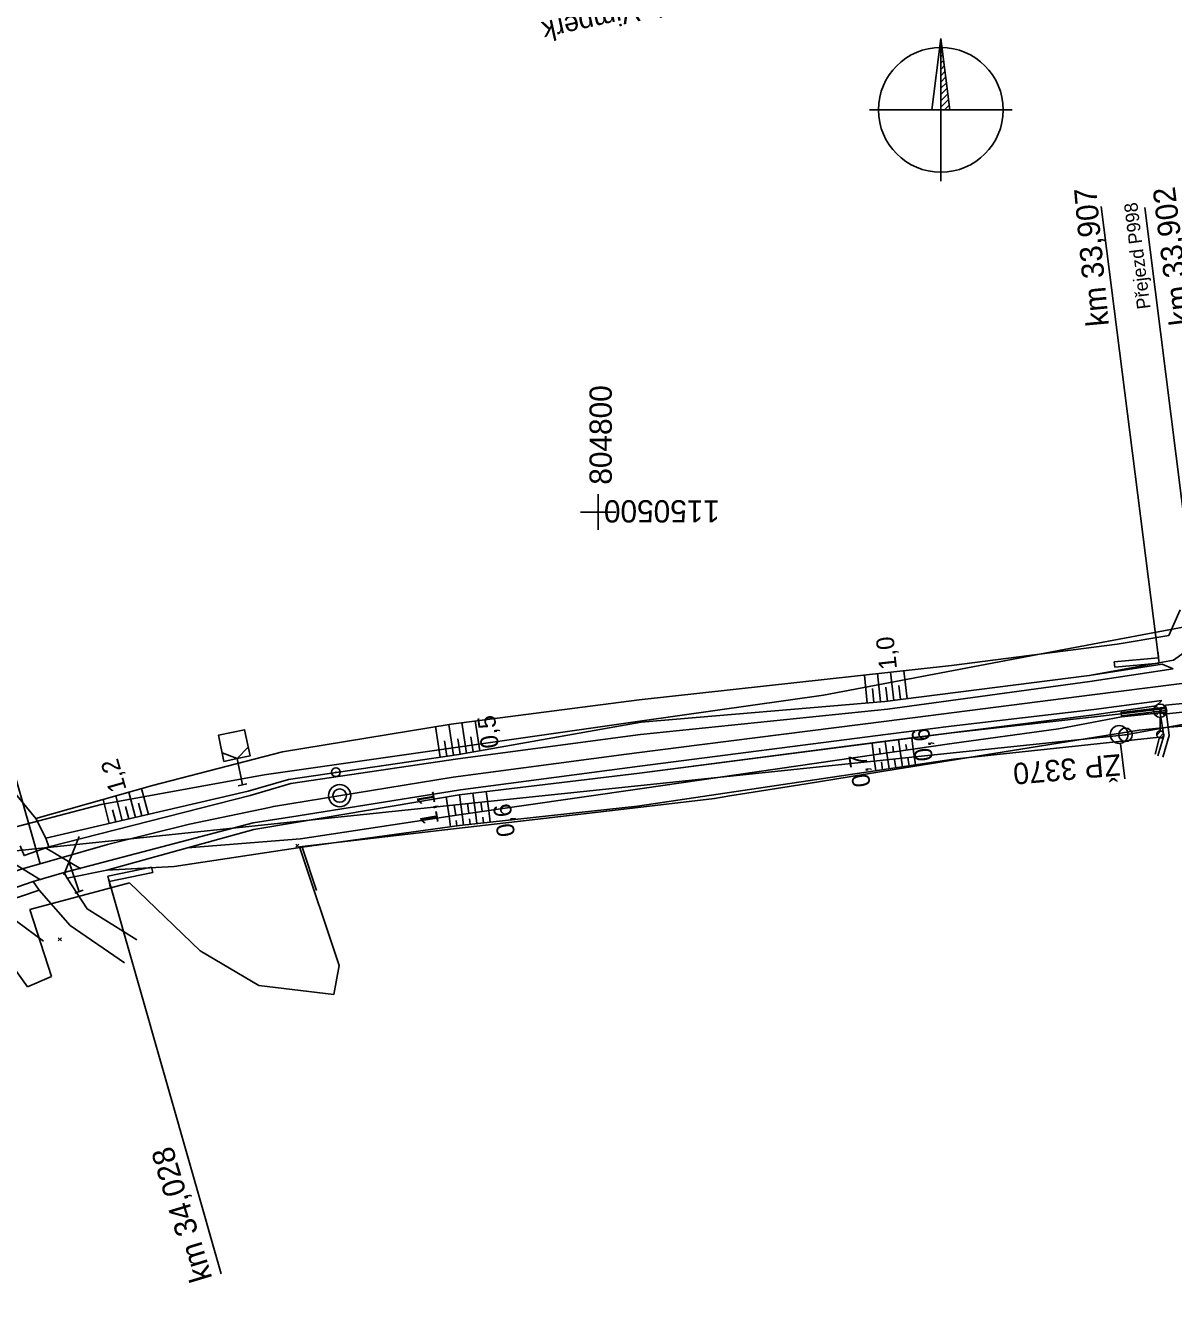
# Model space of a CAD drawing. Extents: x -805730 to -804640, y -1150889 to -1150366.
# Drawn here: x -804864.2 to -804735.5, y -1150590.3 to -1150445.4 of the extents above; entities that cross this region are included whole.
import ezdxf

# ---------------------------------------------------------------- set-up
doc = ezdxf.new("R2010")
doc.units = 0
for name, color, linetype in [('0381KM032-037P - Vrstva 1', 7, 'Continuous'), ('0381KM032-037P - Vrstva 13', 7, 'Continuous'), ('0381KM032-037P - Vrstva 17', 7, 'Continuous'), ('0381KM032-037P - Vrstva 25', 7, 'Continuous'), ('0381KM032-037P - Vrstva 36', 7, 'Continuous'), ('0381KM032-037P - Vrstva 4', 7, 'Continuous'), ('0381KM032-037P - Vrstva 43', 7, 'Continuous'), ('0381KM032-037P - Vrstva 48', 7, 'Continuous'), ('0381KM032-037P - Vrstva 49', 7, 'Continuous'), ('0381KM032-037P - Vrstva 51', 7, 'Continuous'), ('0381KM032-037P - Vrstva 7', 7, 'Continuous'), ('0381KM032-037P - Vrstva 9', 7, 'Continuous'), ('formát', 7, 'Continuous'), ('hran DP - hran DP', 7, 'Continuous'), ('krizky_1000 - souradnice', 7, 'Continuous'), ('krizky_1000 - Vrstva 1', 7, 'Continuous'), ('legenda - Vrstva 7', 7, 'Continuous'), ('vyt_sit - polygon', 7, 'Continuous'), ('vyt_sit - stávající', 7, 'Continuous')]:
    doc.layers.add(name, color=color, linetype=linetype)

msp = doc.modelspace()

# ---------------------------------------------------------------- linework, layer by layer
at = {"layer": '0381KM032-037P - Vrstva 1'}
for points in [[(-804673.35, -1150511.49), (-804675.7, -1150511.78), (-804698.85, -1150514.71), (-804701.61, -1150515.06), (-804722.18, -1150517.67), (-804729.05, -1150518.54), (-804735.1, -1150519.31), (-804744.56, -1150520.5), (-804767.65, -1150523.46), (-804791, -1150526.42)], [(-804791, -1150526.42), (-804796.82, -1150527.16), (-804816.26, -1150529.72), (-804836.43, -1150533.03), (-804836.89, -1150533.13)], [(-804836.89, -1150533.13), (-804845.84, -1150535.01), (-804855.06, -1150537.3), (-804860.78, -1150538.93), (-804864.46, -1150539.98), (-804872.35, -1150542.54)]]:
    msp.add_lwpolyline(points, dxfattribs=at)
at = {"layer": '0381KM032-037P - Vrstva 13'}
msp.add_line((-804736.93, -1150522.56), (-804736.22, -1150522.62), dxfattribs=at)
for points in [[(-804736.32, -1150521.88), (-804741.33, -1150522.48), (-804741.32, -1150522.62), (-804736.39, -1150522.04)], [(-804736.33, -1150522.27), (-804741.29, -1150522.87), (-804741.32, -1150522.62)], [(-804741.29, -1150522.87), (-804741.28, -1150522.98), (-804736.24, -1150522.43)], [(-804736.93, -1150522.56), (-804736.54, -1150525.1), (-804737.22, -1150527.34)], [(-804736.22, -1150522.62), (-804735.92, -1150525.05), (-804736.64, -1150527.49)], [(-804736.32, -1150521.88), (-804736.39, -1150522.04), (-804736.33, -1150522.27), (-804736.24, -1150522.43)]]:
    msp.add_lwpolyline(points, dxfattribs=at)
at = {"layer": '0381KM032-037P - Vrstva 17'}
msp.add_line((-804831.6, -1150542.45), (-804833.23, -1150537.58), dxfattribs=at)
for points in [[(-804734.71, -1150510.96), (-804735.96, -1150513.84), (-804741.77, -1150514.83), (-804760.36, -1150517.2), (-804795.4, -1150521.06), (-804816.51, -1150523.78), (-804835.4, -1150526.88), (-804850, -1150530.66), (-804863.08, -1150534.36), (-804866.23, -1150530.55), (-804868.05, -1150528.28)], [(-804833.23, -1150537.58), (-804815.54, -1150535.16), (-804795.6, -1150532.98), (-804760.14, -1150527.72), (-804737.02, -1150525.24), (-804737.52, -1150527.15)]]:
    msp.add_lwpolyline(points, dxfattribs=at)
at = {"layer": '0381KM032-037P - Vrstva 25'}
for p, q in [((-804737.43, -1150521.73), (-804736.43, -1150522.84)), ((-804737.41, -1150522.86), (-804736.43, -1150521.74)), ((-804736.93, -1150523.04), (-804736.93, -1150524.54)), ((-804737.32, -1150525.02), (-804736.85, -1150524.55)), ((-804737.06, -1150525.32), (-804736.56, -1150524.82))]:
    msp.add_line(p, q, dxfattribs=at)
for centre, radius in [((-804736.94, -1150522.29), 0.749), ((-804736.93, -1150524.94), 0.4), ((-804736.93, -1150524.94), 0.4)]:
    msp.add_circle(centre, radius, dxfattribs=at)
at = {"layer": '0381KM032-037P - Vrstva 36'}
for p, q in [((-804741.54, -1150524.95), (-804741.54, -1150524.95)), ((-804741.41, -1150525.95), (-804740.91, -1150529.91))]:
    msp.add_line(p, q, dxfattribs=at)
msp.add_circle((-804741.54, -1150524.95), 1, dxfattribs=at)
at = {"layer": '0381KM032-037P - Vrstva 4'}
for p, q in [((-804738.68, -1150465.82), (-804731.99, -1150518.9)), ((-804874.8, -1150496.75), (-804862.62, -1150539.46)), ((-804862.01, -1150537.68), (-804858.05, -1150540.04)), ((-804859.94, -1150540.68), (-804858.22, -1150536.4)), ((-804862.58, -1150541.24), (-804866.52, -1150538.84)), ((-804858.24, -1150542.59), (-804859.36, -1150539.27)), ((-804854.94, -1150541.15), (-804854.94, -1150541.15)), ((-804858.72, -1150542.75), (-804857.77, -1150542.43))]:
    msp.add_line(p, q, dxfattribs=at)
for points in [[(-804735.49, -1150517.59), (-804736.73, -1150517.05), (-804744.9, -1150518.34), (-804767.83, -1150521.26)], [(-804735.49, -1150517.59), (-804744.82, -1150519), (-804767.55, -1150522.1)], [(-804767.83, -1150521.26), (-804795.17, -1150523.55), (-804815.65, -1150527.19), (-804834.76, -1150530), (-804839.27, -1150531.31), (-804861.98, -1150536.58), (-804861.64, -1150537.54)], [(-804736.74, -1150521.15), (-804737.38, -1150521.73), (-804744.34, -1150522.73), (-804767.48, -1150525.67)], [(-804736.74, -1150521.15), (-804744.39, -1150522.13), (-804760.4, -1150524), (-804767.46, -1150524.91)], [(-804767.55, -1150522.1), (-804795.24, -1150524.96), (-804815.73, -1150527.69), (-804834.48, -1150530.44), (-804839.03, -1150531.78), (-804861.64, -1150537.54)], [(-804767.46, -1150524.91), (-804795.31, -1150528.51), (-804815.46, -1150531.15), (-804833.67, -1150534.06), (-804838.71, -1150534.85), (-804859.92, -1150540.42), (-804859.57, -1150541.07)], [(-804767.48, -1150525.67), (-804795.35, -1150529.3), (-804815.58, -1150531.71), (-804833.51, -1150534.75), (-804838.64, -1150535.6), (-804846.07, -1150537.67)], [(-804859.57, -1150541.07), (-804855.14, -1150540.16), (-804846.07, -1150537.67)], [(-804862.73, -1150542.41), (-804863.39, -1150541.46), (-804892.29, -1150551.48), (-804910.22, -1150558.86), (-804951.61, -1150576.23), (-804993.7, -1150593.96), (-805038.63, -1150612.92), (-805049.62, -1150617.53), (-805055.59, -1150619.94), (-805066.74, -1150624.75), (-805096.44, -1150637.01)], [(-804864.94, -1150543.15), (-804862.73, -1150542.41), (-804862.73, -1150542.41)]]:
    msp.add_lwpolyline(points, dxfattribs=at)
at = {"layer": '0381KM032-037P - Vrstva 43'}
msp.add_lwpolyline([(-804736.33, -1150521.65), (-804729.5, -1150520.98), (-804729.45, -1150521.92), (-804736.22, -1150522.62)], close=True, dxfattribs=at)
at = {"layer": '0381KM032-037P - Vrstva 48'}
for p, q in [((-804769.83, -1150521.43), (-804770.13, -1150518.28)), ((-804768.33, -1150521.3), (-804768.64, -1150518.12)), ((-804766.81, -1150521.13), (-804767.19, -1150517.96)), ((-804765.32, -1150520.94), (-804765.7, -1150517.79)), ((-804769.08, -1150521.37), (-804769.23, -1150519.78)), ((-804767.55, -1150521.23), (-804767.74, -1150519.63)), ((-804766.07, -1150521.04), (-804766.25, -1150519.46)), ((-804817.72, -1150527.49), (-804818.25, -1150524.06)), ((-804816.23, -1150527.27), (-804816.77, -1150523.82)), ((-804814.76, -1150527.03), (-804815.28, -1150523.62)), ((-804813.28, -1150526.77), (-804813.79, -1150523.43)), ((-804816.97, -1150527.38), (-804817.24, -1150525.66)), ((-804815.5, -1150527.16), (-804815.76, -1150525.44)), ((-804814.02, -1150526.9), (-804814.28, -1150525.21)), ((-804769.09, -1150527.24), (-804769.27, -1150525.92)), ((-804767.6, -1150527.03), (-804767.78, -1150525.73)), ((-804766.12, -1150526.81), (-804766.3, -1150525.53)), ((-804765.38, -1150526.7), (-804765.46, -1150526.07)), ((-804764.64, -1150526.59), (-804764.81, -1150525.34)), ((-804768.83, -1150529.01), (-804769.09, -1150527.24)), ((-804768.35, -1150527.13), (-804768.44, -1150526.48)), ((-804767.35, -1150528.79), (-804767.61, -1150527.03)), ((-804766.86, -1150526.92), (-804766.95, -1150526.27)), ((-804765.87, -1150528.57), (-804766.12, -1150526.81)), ((-804765.12, -1150528.46), (-804765.25, -1150527.58)), ((-804764.38, -1150528.35), (-804764.64, -1150526.59)), ((-804768.09, -1150528.9), (-804768.22, -1150528.02)), ((-804766.61, -1150528.68), (-804766.74, -1150527.8)), ((-804853.39, -1150534.59), (-804854.11, -1150531.82)), ((-804851.93, -1150534.25), (-804852.66, -1150531.42)), ((-804850.47, -1150533.91), (-804851.22, -1150531.01)), ((-804815.25, -1150533.89), (-804815.54, -1150531.71)), ((-804813.77, -1150533.68), (-804814.05, -1150531.53)), ((-804812.28, -1150533.47), (-804812.56, -1150531.35)), ((-804854.85, -1150534.93), (-804855.55, -1150532.23)), ((-804854.12, -1150534.76), (-804854.48, -1150533.4)), ((-804852.66, -1150534.42), (-804853.02, -1150533.02)), ((-804851.2, -1150534.08), (-804851.57, -1150532.65)), ((-804816.7, -1150534.11), (-804817.05, -1150531.96)), ((-804815.96, -1150534), (-804816.14, -1150532.92)), ((-804814.51, -1150533.79), (-804814.65, -1150532.7)), ((-804813.02, -1150533.57), (-804813.16, -1150532.51)), ((-804816.58, -1150535.3), (-804816.73, -1150534.11)), ((-804815.84, -1150535.2), (-804815.92, -1150534.6)), ((-804815.1, -1150535.11), (-804815.25, -1150533.89)), ((-804814.35, -1150535.03), (-804814.43, -1150534.41)), ((-804813.6, -1150534.95), (-804813.76, -1150533.68)), ((-804812.86, -1150534.87), (-804812.94, -1150534.22)), ((-804812.11, -1150534.78), (-804812.28, -1150533.47))]:
    msp.add_line(p, q, dxfattribs=at)
at = {"layer": '0381KM032-037P - Vrstva 49'}
for p, q in [((-804861.98, -1150536.58), (-804863.08, -1150534.36)), ((-804833.93, -1150537.24), (-804833.57, -1150537.6)), ((-804833.57, -1150537.24), (-804833.92, -1150537.6)), ((-804855.14, -1150540.16), (-804859.57, -1150541.07)), ((-804860.23, -1150547.75), (-804860.58, -1150548.11)), ((-804860.58, -1150547.76), (-804860.23, -1150548.11))]:
    msp.add_line(p, q, dxfattribs=at)
for points in [[(-804731.33, -1150510.42), (-804733.06, -1150514.89), (-804735.43, -1150516.61), (-804744.9, -1150518.34), (-804767.83, -1150521.26), (-804795.17, -1150523.55), (-804815.65, -1150527.19), (-804834.76, -1150530), (-804839.27, -1150531.31), (-804861.98, -1150536.58)], [(-804735.96, -1150513.84), (-804741.77, -1150514.83), (-804760.36, -1150517.2), (-804795.4, -1150521.06), (-804816.51, -1150523.78), (-804835.4, -1150526.88), (-804850, -1150530.66), (-804863.08, -1150534.36)], [(-804741.32, -1150522.62), (-804760.31, -1150524.76), (-804795.35, -1150529.3), (-804815.58, -1150531.71), (-804833.51, -1150534.75), (-804838.64, -1150535.6), (-804846.07, -1150537.67)], [(-804846.07, -1150537.67), (-804833.4, -1150536.66), (-804815.63, -1150533.95), (-804795.08, -1150531.02), (-804760.31, -1150525.97), (-804748.35, -1150524.3), (-804741.28, -1150522.98)], [(-804741.32, -1150522.62), (-804741.29, -1150522.87), (-804741.28, -1150522.98)], [(-804737.02, -1150525.24), (-804760.14, -1150527.72), (-804795.6, -1150532.98), (-804815.54, -1150535.16), (-804833.23, -1150537.58)], [(-804833.23, -1150537.58), (-804847.59, -1150539.77), (-804855.14, -1150540.16)], [(-804859.57, -1150541.07), (-804857.34, -1150544.52), (-804851.77, -1150547.99)], [(-804869.27, -1150544.65), (-804865.03, -1150543.19), (-804864.94, -1150543.15), (-804862.73, -1150542.41)], [(-804862.73, -1150542.41), (-804859.23, -1150546.38), (-804853.15, -1150550.59)], [(-804865.78, -1150545.2), (-804865.26, -1150545.89), (-804862.25, -1150548.13)]]:
    msp.add_lwpolyline(points, dxfattribs=at)
at = {"layer": '0381KM032-037P - Vrstva 51'}
msp.add_line((-804861.98, -1150536.58), (-804863.08, -1150534.36), dxfattribs=at)
for points in [[(-804736.22, -1150522.62), (-804735.92, -1150525.05), (-804736.64, -1150527.49)], [(-804861.98, -1150536.58), (-804861.64, -1150537.54), (-804864.42, -1150538.53), (-804864.84, -1150537.45)], [(-804859.57, -1150541.07), (-804859.92, -1150540.42), (-804863.39, -1150541.46), (-804862.73, -1150542.41)], [(-804859.57, -1150541.07), (-804857.34, -1150544.52), (-804851.77, -1150547.99)], [(-804853.15, -1150550.59), (-804859.23, -1150546.38), (-804862.73, -1150542.41)]]:
    msp.add_lwpolyline(points, dxfattribs=at)
at = {"layer": '0381KM032-037P - Vrstva 7'}
for p, q in [((-804840.52, -1150527.66), (-804839.9, -1150530.59)), ((-804840.39, -1150530.7), (-804839.41, -1150530.49)), ((-804829.48, -1150529.18), (-804829.38, -1150529.18))]:
    msp.add_line(p, q, dxfattribs=at)
for points in [[(-804840.52, -1150527.66), (-804839.05, -1150527.35), (-804839.67, -1150524.41), (-804842.6, -1150525.03), (-804841.99, -1150527.97), (-804840.52, -1150527.66)], [(-804842.19, -1150526.99), (-804840.52, -1150527.66), (-804839.26, -1150526.37)]]:
    msp.add_lwpolyline(points, dxfattribs=at)
for centre, radius in [((-804829.43, -1150529.18), 0.5), ((-804829, -1150531.81), 1.25), ((-804829, -1150531.81), 0.752)]:
    msp.add_circle(centre, radius, dxfattribs=at)
at = {"layer": '0381KM032-037P - Vrstva 9'}
for p, q in [((-804737.08, -1150516.65), (-804743.56, -1150465.71)), ((-804737.11, -1150516.35), (-804737.17, -1150515.76)), ((-804737.11, -1150516.35), (-804742.09, -1150516.81)), ((-804742.09, -1150516.81), (-804742.04, -1150517.41)), ((-804742.04, -1150517.41), (-804737.06, -1150516.95)), ((-804737.06, -1150516.95), (-804737.11, -1150516.35)), ((-804850.11, -1150539.83), (-804855, -1150540.85)), ((-804854.88, -1150541.44), (-804849.98, -1150540.42)), ((-804849.98, -1150540.42), (-804850.11, -1150539.83)), ((-804855, -1150540.85), (-804854.88, -1150541.44)), ((-804854.94, -1150541.15), (-804842.3, -1150585.48)), ((-804854.88, -1150541.44), (-804854.75, -1150542.03))]:
    msp.add_line(p, q, dxfattribs=at)
at = {"layer": 'formát'}
for p, q in [((-804761.55, -1150446.86), (-804761.55, -1150462.86)), ((-804761.55, -1150447.49), (-804761.48, -1150447.42)), ((-804761.55, -1150448.2), (-804761.41, -1150448.05)), ((-804761.55, -1150448.91), (-804761.33, -1150448.68)), ((-804761.55, -1150449.61), (-804761.25, -1150449.31)), ((-804761.55, -1150450.32), (-804761.17, -1150449.94)), ((-804761.55, -1150451.03), (-804761.09, -1150450.56)), ((-804761.55, -1150451.74), (-804761.01, -1150451.19)), ((-804761.55, -1150452.44), (-804760.93, -1150451.82)), ((-804761.55, -1150453.15), (-804760.86, -1150452.45)), ((-804761.55, -1150453.86), (-804760.78, -1150453.08)), ((-804769.55, -1150454.86), (-804753.55, -1150454.86)), ((-804761.55, -1150454.56), (-804760.7, -1150453.71)), ((-804761.14, -1150454.86), (-804760.62, -1150454.34))]:
    msp.add_line(p, q, dxfattribs=at)
for points in [[(-804761.55, -1150446.86), (-804762.55, -1150454.86)], [(-804761.55, -1150446.86), (-804760.55, -1150454.86)], [(-804761.55, -1150446.86), (-804761.55, -1150454.86), (-804760.55, -1150454.86), (-804761.55, -1150446.86)]]:
    msp.add_lwpolyline(points, dxfattribs=at)
msp.add_circle((-804761.55, -1150454.86), 7, dxfattribs=at)
at = {"layer": 'hran DP - hran DP'}
for p, q in [((-804747.72, -1150515.43), (-804723.03, -1150510.78)), ((-804774.72, -1150520.52), (-804747.72, -1150515.43)), ((-804795.05, -1150523.42), (-804774.72, -1150520.52)), ((-804837.49, -1150529.49), (-804795.05, -1150523.42)), ((-804739.31, -1150524.46), (-804744.2, -1150525.25)), ((-804736.36, -1150524.18), (-804739.31, -1150524.46)), ((-804729.97, -1150523.63), (-804736.36, -1150524.18)), ((-804744.2, -1150525.25), (-804766.8, -1150528.89)), ((-804766.8, -1150528.89), (-804776.65, -1150530.47)), ((-804855.75, -1150532.82), (-804837.49, -1150529.49)), ((-804776.65, -1150530.47), (-804785.22, -1150531.85)), ((-804785.22, -1150531.85), (-804786.96, -1150532.13)), ((-804868.93, -1150536.25), (-804855.75, -1150532.82)), ((-804795.52, -1150533.13), (-804807.75, -1150534.56)), ((-804786.96, -1150532.13), (-804795.52, -1150533.13)), ((-804807.75, -1150534.56), (-804817.19, -1150535.66)), ((-804817.19, -1150535.66), (-804833.21, -1150537.53)), ((-804833.21, -1150537.53), (-804833.52, -1150537.57)), ((-804833.52, -1150537.57), (-804829.05, -1150550.88)), ((-804852.58, -1150541.61), (-804863.76, -1150544.6)), ((-804844.64, -1150549.24), (-804852.58, -1150541.61)), ((-804863.76, -1150544.6), (-804861.34, -1150552.12)), ((-804864.02, -1150553.26), (-804868.47, -1150547.08)), ((-804838.07, -1150553.11), (-804844.64, -1150549.24)), ((-804861.34, -1150552.12), (-804864.02, -1150553.26)), ((-804829.05, -1150550.88), (-804829.67, -1150554.12)), ((-804829.67, -1150554.12), (-804838.07, -1150553.11))]:
    msp.add_line(p, q, dxfattribs=at)
at = {"layer": 'krizky_1000 - Vrstva 1'}
for points in [[(-804800, -1150498), (-804800, -1150502)], [(-804802, -1150500), (-804798, -1150500)]]:
    msp.add_lwpolyline(points, dxfattribs=at)
at = {"layer": 'vyt_sit - polygon'}
for p, q in [((-804740.83, -1150524.99), (-804673.06, -1150512.75)), ((-804870.84, -1150538.58), (-804740.83, -1150524.99))]:
    msp.add_line(p, q, dxfattribs=at)
at = {"layer": 'vyt_sit - stávající'}
msp.add_line((-804740.89, -1150524.99), (-804740.79, -1150524.99), dxfattribs=at)
msp.add_circle((-804740.83, -1150524.99), 0.756, dxfattribs=at)

# ---------------------------------------------------------------- texts
at = {"layer": '0381KM032-037P - Vrstva 4'}
for s, height, p in [('km 33,902', 2.5, (-804733.36, -1150478.88)), ('Přejezd P998', 1.5, (-804738.02, -1150477.13))]:
    msp.add_text(s, height=height, rotation=97.1938, dxfattribs=at).set_placement(p)
at = {"layer": '0381KM032-037P - Vrstva 48'}
for s, rotation, p in [('1,0', 96.2855, (-804766.46, -1150517.56)), ('0,5', 97.3237, (-804811.13, -1150526.38)), ('0,6', 97.4164, (-804762.42, -1150527.82)), ('0,7', 98.2601, (-804769.42, -1150530.71)), ('1,2', 105.8168, (-804852.9, -1150531.1)), ('1,1', 99.611, (-804817.86, -1150534.9)), ('0,6', 98.12, (-804809.31, -1150536.28))]:
    msp.add_text(s, height=2, rotation=rotation, dxfattribs=at).set_placement(p)
at = {"layer": '0381KM032-037P - Vrstva 9'}
for s, rotation, p in [('km 33,907', 95.2837, (-804742.69, -1150479.05)), ('km 34,028', 106.8099, (-804843.28, -1150585.95))]:
    msp.add_text(s, height=2.5, rotation=rotation, dxfattribs=at).set_placement(p)
at = {"layer": 'krizky_1000 - souradnice'}
for s, rotation, p in [('804800', 90, (-804798.47, -1150496.92)), ('1150500', 180, (-804786.34, -1150498.66))]:
    msp.add_text(s, height=2.5, rotation=rotation, dxfattribs=at).set_placement(p)
at = {"layer": 'legenda - Vrstva 7'}
msp.add_text('k.ú. Vimperk', height=2.25, rotation=192.4227, dxfattribs=at).set_placement((-804790.13, -1150441.44))
at = {"layer": 'vyt_sit - stávající'}
msp.add_text('ŽP 3370', height=2.4, rotation=185, dxfattribs=at).set_placement((-804741.45, -1150527.14))

doc.saveas('drawing.dxf')
